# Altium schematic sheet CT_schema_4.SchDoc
size 573 x 363 mm
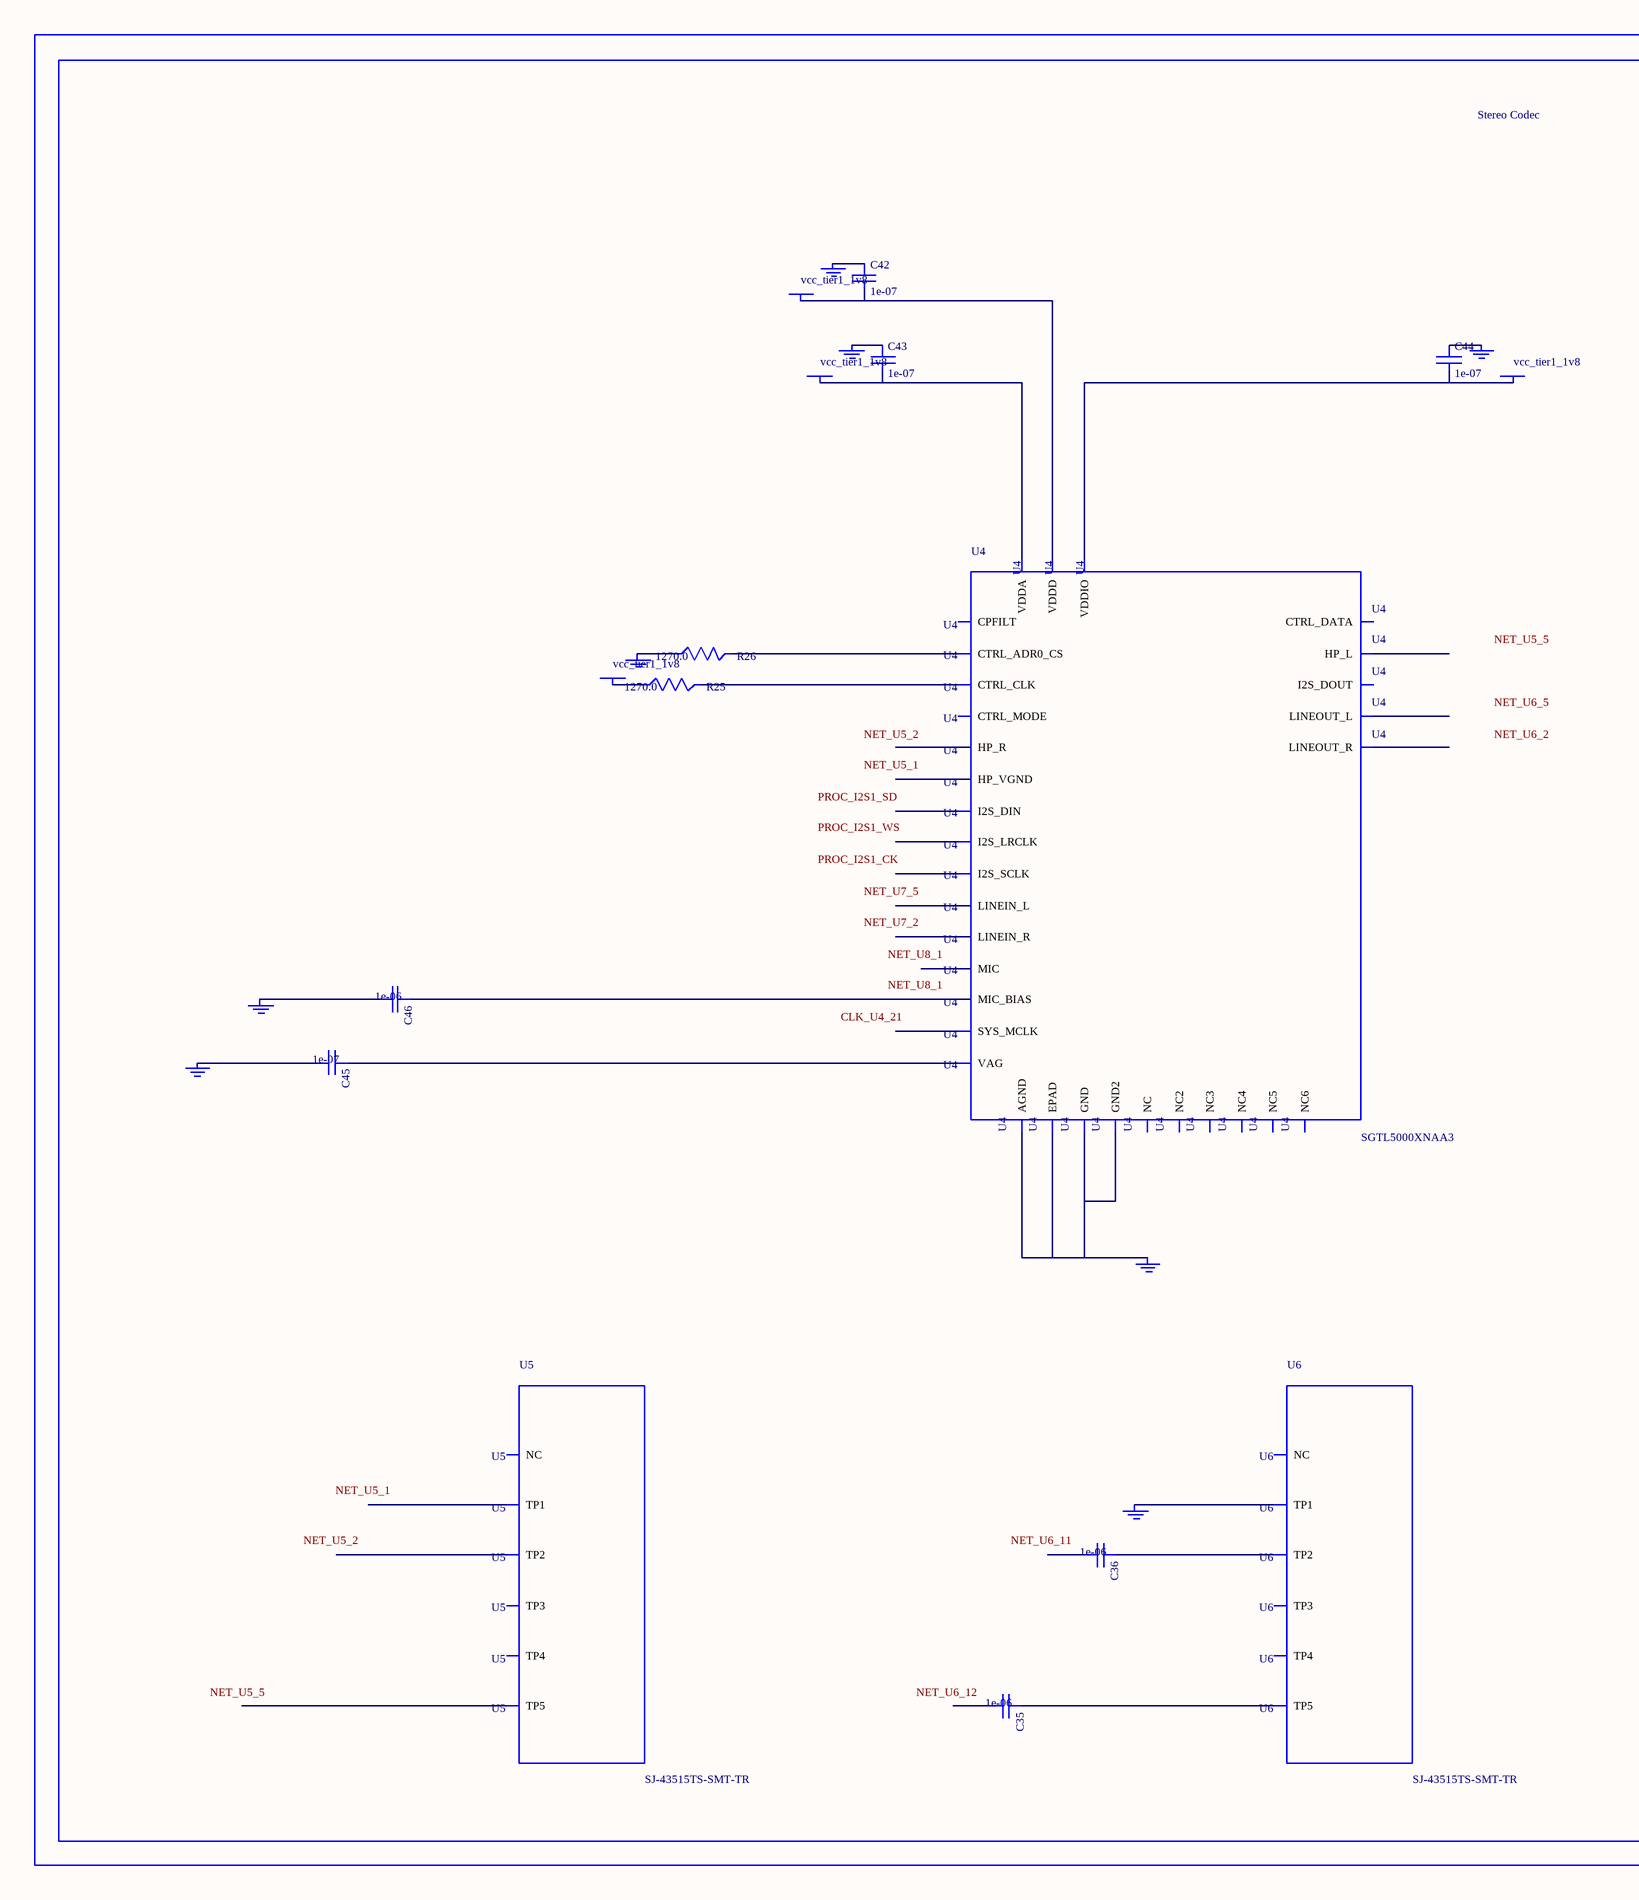
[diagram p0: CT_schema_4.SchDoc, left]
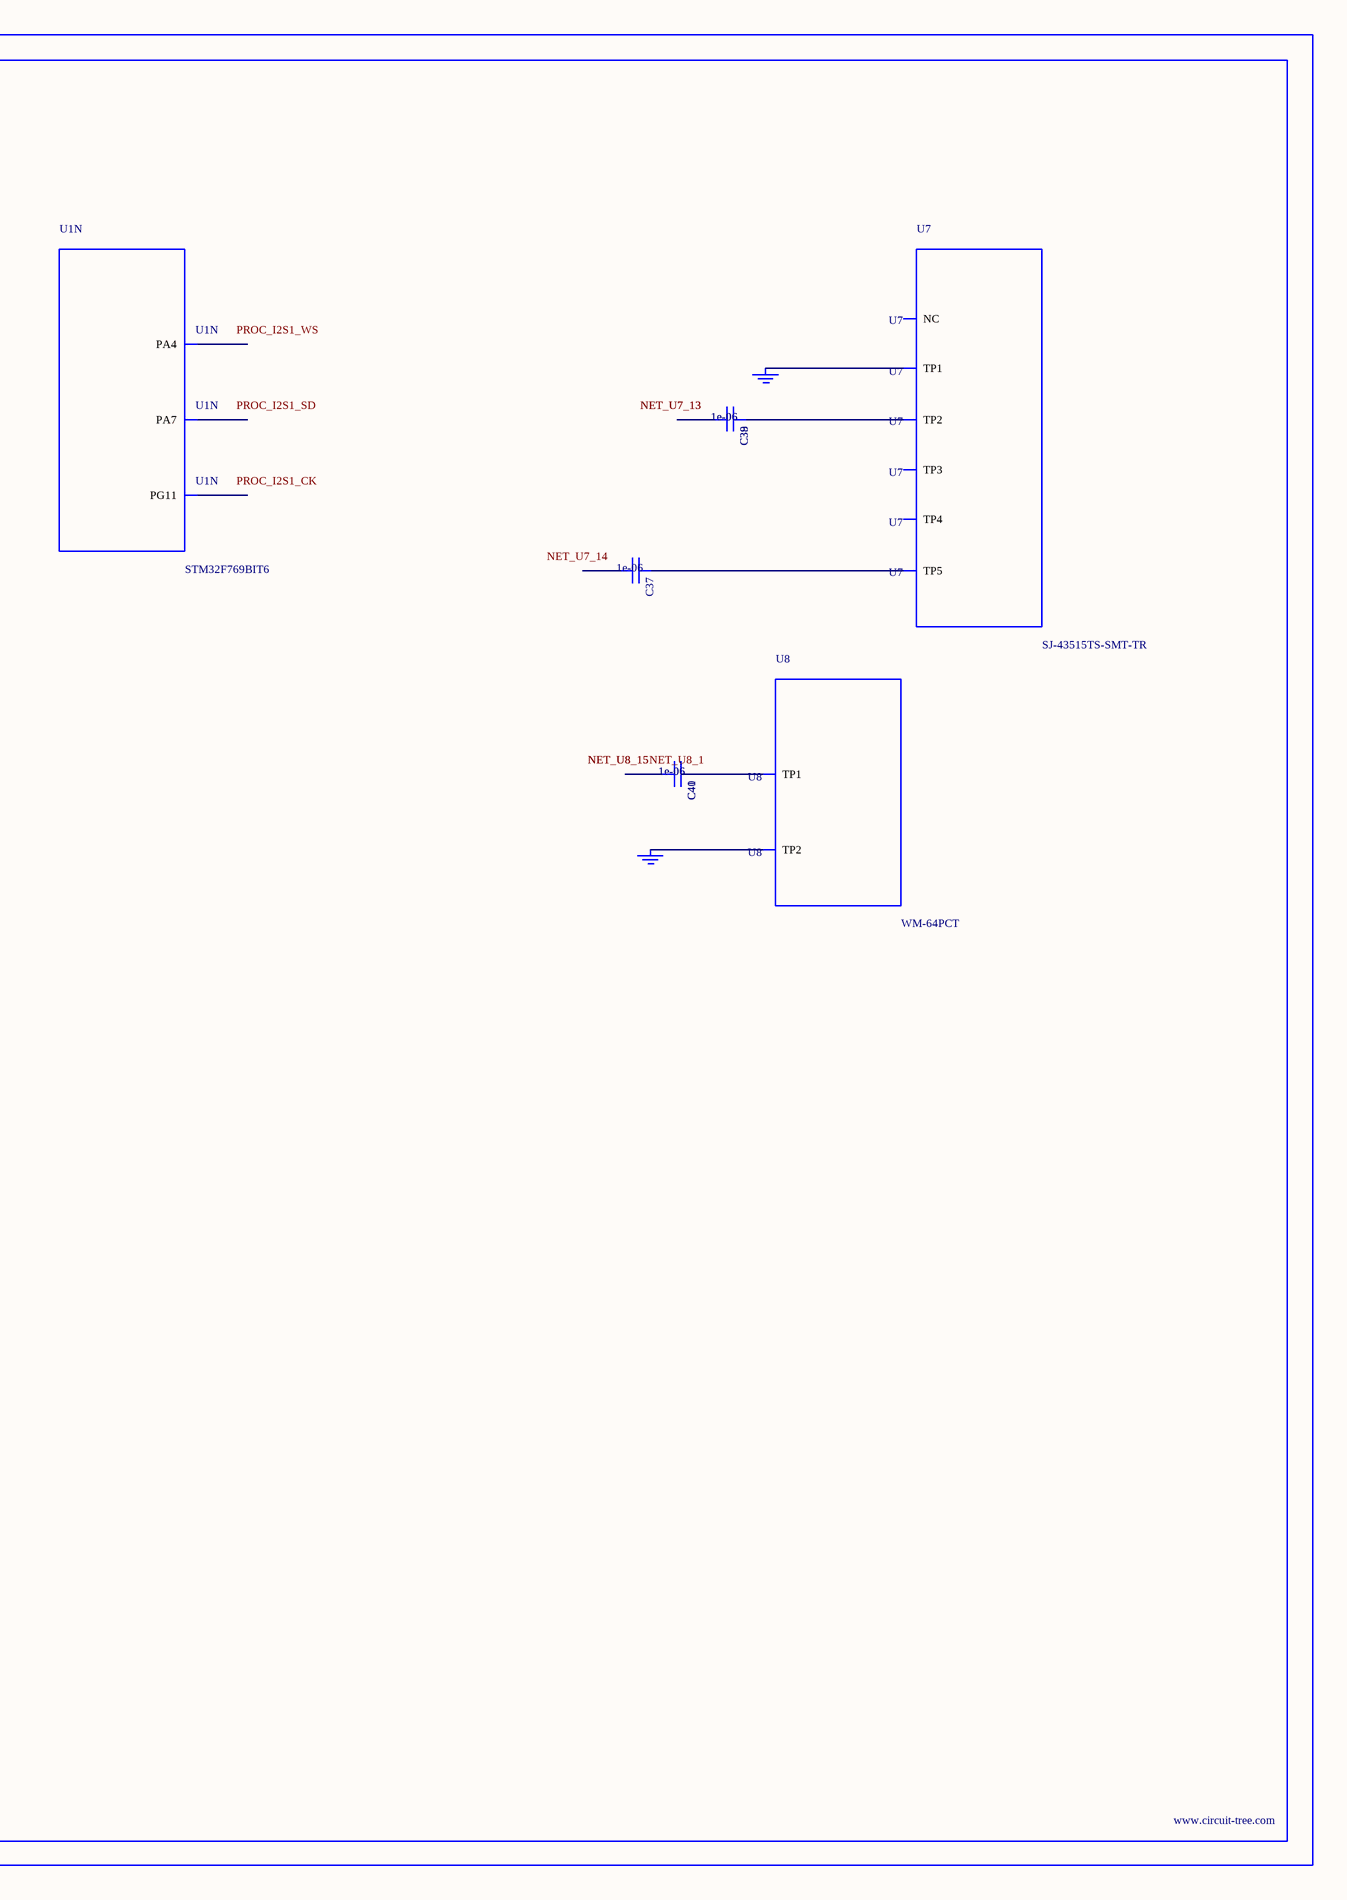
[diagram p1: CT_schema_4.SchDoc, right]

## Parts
BORDER3  (no value)
C35  1e-06  [C0603]
C36  1e-06  [C0603]
C37  1e-06  [C0603]
C38  1e-06  [C0603]
C39  1e-06  [C0603]
C40  1e-06  [C0603]
C41  1e-06  [C0603]
C42  1e-07  [C0402]
C43  1e-07  [C0402]
C44  1e-07  [C0402]
C45  1e-07  [C0402]
C46  1e-06  [C0603]
GND_INSTANCE_3_0  (no value)
GND_INSTANCE_3_1  (no value)
GND_INSTANCE_3_2  (no value)
GND_INSTANCE_3_3  (no value)
GND_INSTANCE_3_4  (no value)
GND_INSTANCE_3_5  (no value)
GND_INSTANCE_3_6  (no value)
GND_INSTANCE_3_7  (no value)
GND_INSTANCE_3_8  (no value)
GND_INSTANCE_3_9  (no value)
GND_INSTANCE_3_10  (no value)
POWER_INSTANCE_3_0  vcc_tier1_1v8
POWER_INSTANCE_3_1  vcc_tier1_1v8
POWER_INSTANCE_3_2  vcc_tier1_1v8
POWER_INSTANCE_3_3  vcc_tier1_1v8
R25  1270.0  [R0603]
R26  1270.0  [R0603]
U1  STM32F769BIT6  [LQFP208]  (part N of 15)
U4  SGTL5000XNAA3  [QFN-32]
U5  SJ-43515TS-SMT-TR  [SJ-43515TS-SMT-TR]
U6  SJ-43515TS-SMT-TR  [SJ-43515TS-SMT-TR]
U7  SJ-43515TS-SMT-TR  [SJ-43515TS-SMT-TR]
U8  WM-64PCT  [WM-64PC]

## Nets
NetC35_1: C35.1 U6.5(TP5)
NetC36_1: C36.1 U6.2(TP2)
NetC37_1: C37.1 U7.5(TP5)
NetC38_1: C38.1 C39.1 U7.2(TP2)
NetC38_2: C38.2 C39.2
NetC40_1: C40.1 C41.1 U8.1(TP1)
NetC40_2: C40.2 C41.2
NetC42_1: C42.1 GND_INSTANCE_3_5.0(GND)
NetC42_2: C42.2 POWER_INSTANCE_3_3.0(PWR) U4.30(VDDD)
NetC43_1: C43.1 GND_INSTANCE_3_1.0(GND)
NetC43_2: C43.2 POWER_INSTANCE_3_0.0(PWR) U4.5(VDDA)
NetC44_1: C44.1 GND_INSTANCE_3_4.0(GND)
NetC44_2: C44.2 POWER_INSTANCE_3_1.0(PWR) U4.20(VDDIO)
NetC45_1: C45.1 U4.10(VAG)
NetC45_2: C45.2 GND_INSTANCE_3_2.0(GND)
NetC46_1: C46.1 U4.16(MIC_BIAS)
NetC46_2: C46.2 GND_INSTANCE_3_3.0(GND)
NetGND_INSTANCE_3_0_0: GND_INSTANCE_3_0.0(GND) U4.1(GND) U4.3(GND2) U4.7(AGND) U4.EXP(EPAD)
NetGND_INSTANCE_3_6_0: GND_INSTANCE_3_6.0(GND) R26.1
NetGND_INSTANCE_3_7_0: GND_INSTANCE_3_7.0(GND) U6.1(TP1)
NetGND_INSTANCE_3_8_0: GND_INSTANCE_3_8.0(GND) GND_INSTANCE_3_9.0(GND) U7.1(TP1)
NetGND_INSTANCE_3_10_0: GND_INSTANCE_3_10.0(GND) U8.2(TP2)
NetPOWER_INSTANCE_3_2_0: POWER_INSTANCE_3_2.0(PWR) R25.1
NetR25_2: R25.2 U4.29(CTRL_CLK)
NetR26_2: R26.2 U4.31(CTRL_ADR0_CS)

Not connected (* = marked no-connect by the designer): C35 2; C36 2; C37 2; U1 53(PA4) 56(PA7) 180(PG11); U4 2(HP_R) 4(HP_VGND) 6(HP_L) 8(NC) 9(NC2) 11(LINEOUT_R) 12(LINEOUT_L) 13(LINEIN_R) 14(LINEIN_L) 15(MIC) 17(NC3) 18(CPFILT) 19(NC4) 21(SYS_MCLK) 22(NC5) 23(I2S_LRCLK) 24(I2S_SCLK) 25(I2S_DOUT) 26(I2S_DIN) 27(CTRL_DATA) 28(NC6) 32(CTRL_MODE); U5 1(TP1) 2(TP2) 3(TP3) 4(TP4) 5(TP5) 6(NC); U6 3(TP3) 4(TP4) 6(NC); U7 3(TP3) 4(TP4) 6(NC)

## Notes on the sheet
- Labels drawn without touching a wire or pin: CLK_U4_21, NET_U5_1, NET_U5_2, NET_U5_5, NET_U6_2, NET_U6_5, NET_U6_11, NET_U6_12, NET_U7_2, NET_U7_5, NET_U7_14, NET_U8_1, PROC_I2S1_CK, PROC_I2S1_SD, PROC_I2S1_WS

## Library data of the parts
BORDER3 = BORDER_PAGE3
C35-C41 C46 = C0603C105K3RACTU
C42-C45 = C0402C104K3RACTU
GND_INSTANCE_3_0-GND_INSTANCE_3_10 = GND
POWER_INSTANCE_3_0-POWER_INSTANCE_3_3 = PWR
R25 R26 = RC0603FR-071K27L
